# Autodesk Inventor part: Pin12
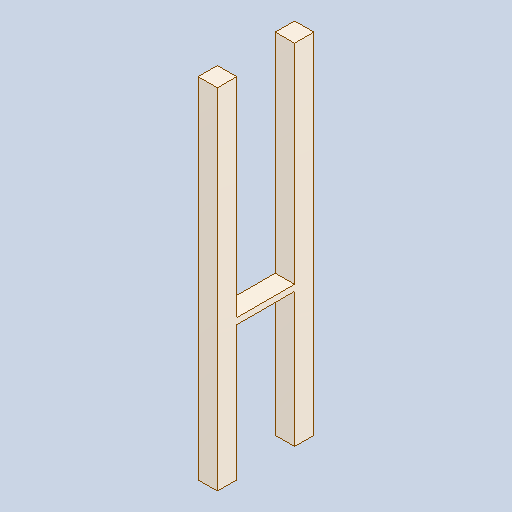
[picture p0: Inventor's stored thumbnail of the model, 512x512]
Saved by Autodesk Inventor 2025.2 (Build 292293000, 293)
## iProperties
Created: 2025-04
Part Number: Pin12
Material: Generic
Description: PART--DESC
Document SubType Name: Modeling
Designer: BennF
Density: 1 g/cm^3
Appearance: Default
Author: BennF
Revision Number: NONE
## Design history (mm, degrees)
feature "Solid"
body "Solid1"
